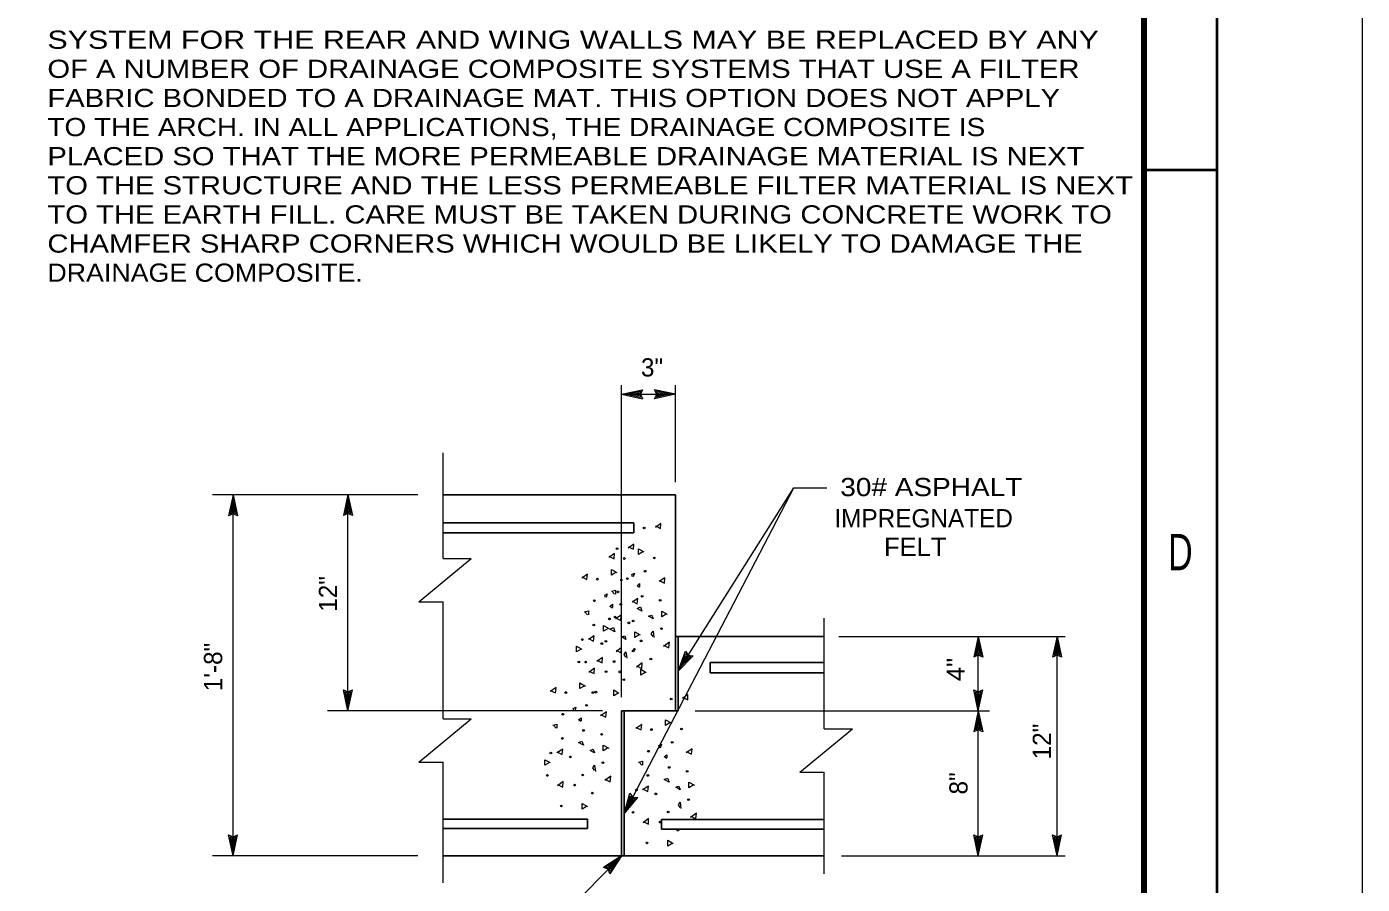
# Model space of a CAD drawing. Extents: x -22.3 to 19.7, y -11.8 to 18.2.
# Drawn here: x 10.52 to 19.69, y 6.25 to 12.14 of the extents above; entities that cross this region are included whole.
import ezdxf
from ezdxf.enums import TextEntityAlignment as Align

# ---------------------------------------------------------------- set-up
doc = ezdxf.new("R2010")
doc.units = 0
doc.header["$LTSCALE"] = 0.05
doc.layers.add('1', color=7, linetype='Continuous', lineweight=13)
doc.layers.add('2', color=7, linetype='Continuous', lineweight=13)

msp = doc.modelspace()

# ---------------------------------------------------------------- linework, layer by layer
at = {"layer": '1', "lineweight": 40}
msp.add_line((18.19058, 11.16031), (18.69058, 11.16031), dxfattribs=at)
at = {"layer": '1'}
for p, q in [((14.60258, 7.53931), (14.60258, 9.68231)), ((14.60358, 9.61931), (14.74758, 9.65031)), ((14.64058, 9.61931), (14.73458, 9.63931)), ((14.73458, 9.63931), (14.72558, 9.61931)), ((14.97458, 9.61931), (14.83058, 9.65031)), ((14.93758, 9.61931), (14.84358, 9.63931)), ((14.85258, 9.61931), (14.84358, 9.63931)), ((14.97458, 9.01431), (14.97458, 9.68231)), ((14.60358, 9.61931), (14.97458, 9.61931)), ((14.60358, 9.61931), (14.74758, 9.58831)), ((14.64058, 9.61931), (14.73458, 9.59931)), ((14.67658, 9.61931), (14.72158, 9.62931)), ((14.67658, 9.61931), (14.72158, 9.61031)), ((14.72158, 9.62931), (14.71758, 9.61931)), ((14.71758, 9.61931), (14.72158, 9.61031)), ((14.72558, 9.61931), (14.73458, 9.59931)), ((14.97458, 9.61931), (14.83058, 9.58831)), ((14.93758, 9.61931), (14.84358, 9.59931)), ((14.84358, 9.59931), (14.85258, 9.61931)), ((14.90158, 9.61931), (14.85658, 9.62831)), ((14.86058, 9.61931), (14.85658, 9.62831)), ((14.90158, 9.61931), (14.85658, 9.60931)), ((14.85658, 9.60931), (14.86058, 9.61931)), ((13.37858, 8.49131), (13.37858, 9.21731)), ((13.20358, 8.92831), (11.79458, 8.92831)), ((11.93558, 8.92831), (11.90458, 8.78431)), ((11.93558, 6.44931), (11.93558, 8.92831)), ((11.93558, 8.92831), (11.96658, 8.78431)), ((12.72458, 8.93031), (12.69358, 8.78631)), ((12.72458, 7.44431), (12.72458, 8.93031)), ((12.72458, 8.93031), (12.75558, 8.78631)), ((14.99158, 7.71731), (15.78558, 8.97631)), ((11.93558, 8.89131), (11.91558, 8.79731)), ((11.93558, 8.80631), (11.91558, 8.79731)), ((11.93558, 8.85531), (11.92658, 8.81031)), ((11.93558, 8.81431), (11.92658, 8.81031)), ((11.93558, 8.89131), (11.95558, 8.79731)), ((11.93558, 8.85531), (11.94558, 8.81031)), ((11.94558, 8.81031), (11.93558, 8.81431)), ((11.95558, 8.79731), (11.93558, 8.80631)), ((12.72458, 8.89331), (12.70458, 8.79931)), ((12.72458, 8.80831), (12.70458, 8.79931)), ((12.72458, 8.85731), (12.71558, 8.81231)), ((12.72458, 8.81631), (12.71558, 8.81231)), ((12.72458, 8.89331), (12.74458, 8.79931)), ((12.72458, 8.85731), (12.73458, 8.81231)), ((12.73458, 8.81231), (12.72458, 8.81631)), ((12.74458, 8.79931), (12.72458, 8.80831)), ((13.21058, 8.19431), (13.57158, 8.49131)), ((13.37858, 8.49131), (13.57158, 8.49131)), ((13.21058, 8.19431), (13.37858, 8.19431)), ((13.37858, 7.38931), (13.37858, 8.19431)), ((15.99558, 7.32131), (15.99558, 8.08231)), ((16.09558, 7.95631), (17.65058, 7.95631)), ((17.05358, 7.95631), (17.02258, 7.81231)), ((17.05358, 7.91931), (17.03358, 7.82531)), ((17.05358, 7.95631), (17.08458, 7.81231)), ((17.05358, 7.91931), (17.07358, 7.82531)), ((17.59458, 7.95731), (17.56358, 7.81331)), ((17.59458, 7.92031), (17.57458, 7.82631)), ((17.59458, 6.44931), (17.59458, 7.95731)), ((17.59458, 7.95731), (17.62558, 7.81331)), ((17.59458, 7.92031), (17.61458, 7.82631)), ((14.99158, 7.71731), (15.04258, 7.85531)), ((14.99158, 7.71731), (15.09458, 7.82231)), ((15.01158, 7.74831), (15.04458, 7.83831)), ((15.01158, 7.74831), (15.07858, 7.81731)), ((15.03058, 7.77931), (15.04558, 7.82231)), ((15.03058, 7.77931), (15.06258, 7.81231)), ((15.04458, 7.83831), (15.05658, 7.82031)), ((15.04558, 7.82231), (15.05258, 7.81331)), ((15.05258, 7.81331), (15.06258, 7.81231)), ((15.05658, 7.82031), (15.07858, 7.81731)), ((17.05358, 7.83431), (17.03358, 7.82531)), ((17.05358, 7.88331), (17.04458, 7.83831)), ((17.05358, 7.84231), (17.04458, 7.83831)), ((17.05358, 7.88331), (17.06358, 7.83831)), ((17.06358, 7.83831), (17.05358, 7.84231)), ((17.07358, 7.82531), (17.05358, 7.83431)), ((17.59458, 7.83531), (17.57458, 7.82631)), ((17.59458, 7.88431), (17.58558, 7.83931)), ((17.59458, 7.84331), (17.58558, 7.83931)), ((17.59458, 7.88431), (17.60458, 7.83931)), ((17.60458, 7.83931), (17.59458, 7.84331)), ((17.61458, 7.82631), (17.59458, 7.83531)), ((12.72458, 7.44431), (12.69358, 7.58831)), ((12.72458, 7.48131), (12.70458, 7.57531)), ((12.70458, 7.57531), (12.72458, 7.56631)), ((12.72458, 7.51731), (12.71458, 7.56231)), ((12.71458, 7.56231), (12.72458, 7.55831)), ((12.72458, 7.44431), (12.75558, 7.58831)), ((12.72458, 7.48131), (12.74458, 7.57531)), ((12.72458, 7.56631), (12.74458, 7.57531)), ((12.72458, 7.51731), (12.73358, 7.56231)), ((12.72458, 7.55831), (12.73358, 7.56231)), ((17.05358, 7.44431), (17.02258, 7.58831)), ((17.05358, 7.48131), (17.03358, 7.57531)), ((17.03358, 7.57531), (17.05358, 7.56631)), ((17.05358, 7.51731), (17.04358, 7.56231)), ((17.04358, 7.56231), (17.05358, 7.55831)), ((17.05358, 7.44431), (17.08458, 7.58831)), ((17.05358, 7.48131), (17.07358, 7.57531)), ((17.05358, 7.56631), (17.07358, 7.57531)), ((17.05358, 7.51731), (17.06258, 7.56231)), ((17.05358, 7.55831), (17.06258, 7.56231)), ((14.47158, 7.44431), (12.58358, 7.44431)), ((15.10958, 7.44431), (17.12958, 7.44431)), ((17.05358, 7.44431), (17.02258, 7.30031)), ((17.05358, 7.44431), (17.08458, 7.30031)), ((13.21058, 7.09231), (13.57158, 7.38931)), ((13.37858, 7.38931), (13.57158, 7.38931)), ((17.05358, 7.40731), (17.03358, 7.31331)), ((17.05358, 7.37131), (17.04458, 7.32631)), ((17.05358, 7.40731), (17.07358, 7.31331)), ((17.05358, 7.37131), (17.06358, 7.32631)), ((15.82758, 7.02431), (16.18858, 7.32131)), ((15.99558, 7.32131), (16.18858, 7.32131)), ((17.05358, 7.32231), (17.03358, 7.31331)), ((17.05358, 7.33031), (17.04458, 7.32631)), ((17.06358, 7.32631), (17.05358, 7.33031)), ((17.07358, 7.31331), (17.05358, 7.32231)), ((13.21058, 7.09231), (13.37858, 7.09231)), ((13.37858, 6.26331), (13.37858, 7.09231)), ((15.82758, 7.02431), (15.99558, 7.02431)), ((15.99558, 6.32531), (15.99558, 7.02431)), ((14.62158, 6.73631), (14.66058, 6.87831)), ((14.62158, 6.73631), (14.71558, 6.84931)), ((14.63858, 6.76931), (14.66458, 6.86131)), ((14.63858, 6.76931), (14.69958, 6.84331)), ((14.65558, 6.80131), (14.66758, 6.84531)), ((14.65558, 6.80131), (14.68358, 6.83731)), ((14.66458, 6.86131), (14.67758, 6.84431)), ((14.66758, 6.84531), (14.67458, 6.83731)), ((14.67458, 6.83731), (14.68358, 6.83731)), ((14.67758, 6.84431), (14.69958, 6.84331)), ((11.93558, 6.44931), (11.90458, 6.59331)), ((11.93558, 6.48631), (11.91558, 6.58031)), ((11.91558, 6.58031), (11.93558, 6.57131)), ((11.93558, 6.52231), (11.92558, 6.56731)), ((11.92558, 6.56731), (11.93558, 6.56331)), ((11.93558, 6.44931), (11.96658, 6.59331)), ((11.93558, 6.48631), (11.95558, 6.58031)), ((11.93558, 6.57131), (11.95558, 6.58031)), ((11.93558, 6.52231), (11.94458, 6.56731)), ((11.93558, 6.56331), (11.94458, 6.56731)), ((17.05358, 6.44931), (17.02258, 6.59331)), ((17.05358, 6.48631), (17.03358, 6.58031)), ((17.03358, 6.58031), (17.05358, 6.57131)), ((17.05358, 6.52231), (17.04358, 6.56731)), ((17.04358, 6.56731), (17.05358, 6.56331)), ((17.05358, 6.44931), (17.08458, 6.59331)), ((17.05358, 6.48631), (17.07358, 6.58031)), ((17.05358, 6.57131), (17.07358, 6.58031)), ((17.05358, 6.52231), (17.06258, 6.56731)), ((17.05358, 6.56331), (17.06258, 6.56731)), ((17.59458, 6.44931), (17.56358, 6.59331)), ((17.59458, 6.48631), (17.57458, 6.58031)), ((17.57458, 6.58031), (17.59458, 6.57131)), ((17.59458, 6.52231), (17.58458, 6.56731)), ((17.58458, 6.56731), (17.59458, 6.56331)), ((17.59458, 6.44931), (17.62558, 6.59331)), ((17.59458, 6.48631), (17.61458, 6.58031)), ((17.59458, 6.57131), (17.61458, 6.58031)), ((17.59458, 6.52231), (17.60358, 6.56731)), ((17.59458, 6.56331), (17.60358, 6.56731)), ((13.20358, 6.44931), (11.79458, 6.44931)), ((14.60258, 6.44931), (14.47958, 6.36831)), ((14.57658, 6.42331), (14.49658, 6.37031)), ((14.60258, 6.44931), (14.52358, 6.32531)), ((14.57658, 6.42331), (14.52558, 6.34231)), ((16.11458, 6.44931), (17.65058, 6.44931)), ((14.51758, 6.36231), (14.49658, 6.37031)), ((14.55158, 6.39731), (14.51358, 6.37131)), ((14.52258, 6.36831), (14.51358, 6.37131)), ((14.52558, 6.34231), (14.51758, 6.36231)), ((14.52658, 6.35831), (14.52258, 6.36831)), ((14.55158, 6.39731), (14.52658, 6.35831))]:
    msp.add_line(p, q, dxfattribs=at)
at = {"layer": '1', "lineweight": 25}
for p, q in [((13.37858, 8.92831), (14.97458, 8.92831)), ((14.97458, 7.44431), (14.97458, 8.92831)), ((13.37858, 8.73631), (14.68858, 8.73631)), ((14.68858, 8.66831), (14.68858, 8.73631)), ((13.37858, 8.66831), (14.68858, 8.66831)), ((14.97458, 7.95631), (15.99558, 7.95631)), ((14.99158, 7.44431), (14.99158, 7.95631)), ((15.21258, 7.77631), (15.99358, 7.77631)), ((15.21258, 7.70531), (15.21258, 7.77631)), ((15.21258, 7.70531), (15.99358, 7.70531)), ((14.60258, 6.44931), (14.60258, 7.44431)), ((14.60258, 7.44431), (14.99158, 7.44431)), ((14.62158, 6.44931), (14.62158, 7.44431)), ((13.37858, 6.70131), (14.37058, 6.70131)), ((14.37058, 6.63631), (14.37058, 6.70131)), ((14.87858, 6.69731), (15.99558, 6.69731)), ((14.87858, 6.63131), (14.87858, 6.69731)), ((13.37858, 6.63631), (14.37058, 6.63631)), ((14.87858, 6.63131), (15.99558, 6.63131)), ((13.37858, 6.44931), (15.99558, 6.44931))]:
    msp.add_line(p, q, dxfattribs=at)
at = {"layer": '1'}
for points in [[(-22.30942, 18.16031), (19.69058, 18.16031), (19.69058, -11.83969)], [(14.74758, 9.65031), (14.73358, 9.61931), (14.74758, 9.58831)], [(14.83058, 9.58831), (14.84458, 9.61931), (14.83058, 9.65031)], [(14.62158, 6.73631), (15.78558, 8.97631), (16.01258, 8.97631)], [(11.96658, 8.78431), (11.93558, 8.79831), (11.90458, 8.78431)], [(12.75558, 8.78631), (12.72458, 8.80031), (12.69358, 8.78631)], [(17.05358, 6.44931), (17.05358, 7.44431), (17.05358, 7.95631)], [(15.04258, 7.85531), (15.06058, 7.82731), (15.09458, 7.82231)], [(17.08458, 7.81231), (17.05358, 7.82631), (17.02258, 7.81231)], [(17.62558, 7.81331), (17.59458, 7.82731), (17.56358, 7.81331)], [(12.69358, 7.58831), (12.72458, 7.57431), (12.75558, 7.58831)], [(17.02258, 7.58831), (17.05358, 7.57431), (17.08458, 7.58831)], [(17.08458, 7.30031), (17.05358, 7.31431), (17.02258, 7.30031)], [(14.66058, 6.87831), (14.68158, 6.85131), (14.71558, 6.84931)], [(11.90458, 6.59331), (11.93558, 6.57931), (11.96658, 6.59331)], [(17.02258, 6.59331), (17.05358, 6.57931), (17.08458, 6.59331)], [(17.56358, 6.59331), (17.59458, 6.57931), (17.62558, 6.59331)], [(14.60258, 6.44931), (13.31658, 5.13931), (12.74958, 5.13931)], [(14.52358, 6.32531), (14.51158, 6.35631), (14.47958, 6.36831)]]:
    msp.add_lwpolyline(points, dxfattribs=at)
at = {"layer": '1', "lineweight": 40}
msp.add_lwpolyline([(-21.30942, -10.83969), (-21.30942, 17.16031), (18.69058, 17.16031), (18.69058, -10.83969)], close=True, dxfattribs=at)
at = {"layer": '1', "lineweight": 90}
msp.add_lwpolyline([(-19.80942, 16.66031), (18.19058, 16.66031), (18.19058, -10.33969), (-19.80942, -10.33969)], close=True, dxfattribs=at)
at = {"layer": '2'}
for p, q in [((14.55558, 8.24631), (14.53758, 8.26631)), ((14.36958, 8.10431), (14.35158, 8.12431)), ((14.15358, 7.32531), (14.13558, 7.34531)), ((14.74158, 7.07131), (14.72358, 7.09131))]:
    msp.add_line(p, q, dxfattribs=at)
for points in [[(14.83558, 8.71431), (14.87158, 8.69631), (14.87358, 8.73231), (14.83558, 8.70431)], [(14.64958, 8.57231), (14.68558, 8.55431), (14.68758, 8.59031), (14.64958, 8.56231)], [(14.74958, 8.53631), (14.71958, 8.51831), (14.71958, 8.55831), (14.75758, 8.53631)], [(14.51558, 8.50631), (14.55158, 8.48831), (14.55558, 8.52631), (14.51558, 8.49831)], [(14.32958, 8.36431), (14.36558, 8.34631), (14.36958, 8.38431), (14.32958, 8.35631)], [(14.56358, 8.39431), (14.53358, 8.37631), (14.53358, 8.41631), (14.57158, 8.39431)], [(14.67958, 8.36431), (14.67358, 8.38231), (14.69158, 8.39031), (14.68358, 8.36431)], [(14.86158, 8.34031), (14.89758, 8.32231), (14.90158, 8.35831), (14.86158, 8.33231)], [(14.53358, 8.26631), (14.56158, 8.27431), (14.56158, 8.24631)], [(14.72758, 8.29231), (14.70958, 8.30431), (14.72758, 8.31831), (14.72758, 8.29631)], [(14.49358, 8.22231), (14.48758, 8.24031), (14.50558, 8.24831), (14.49758, 8.22231)], [(14.54158, 8.15031), (14.52358, 8.16231), (14.54158, 8.17631), (14.54158, 8.15431)], [(14.67558, 8.19831), (14.71158, 8.18031), (14.71558, 8.21631), (14.67558, 8.19031)], [(14.34758, 8.12431), (14.37558, 8.13231), (14.37558, 8.10431)], [(14.56158, 8.08431), (14.59758, 8.06631), (14.60158, 8.10231), (14.56158, 8.07631)], [(14.90958, 8.10831), (14.87958, 8.09031), (14.87958, 8.13031), (14.91758, 8.10831)], [(14.51158, 8.01031), (14.47958, 7.99231), (14.47958, 8.03031), (14.51558, 8.01031)], [(14.72358, 7.96631), (14.69358, 7.94831), (14.69358, 7.98831), (14.73158, 7.96631)], [(14.81958, 7.95631), (14.80758, 7.97431), (14.81958, 7.99231), (14.82558, 7.94831)], [(14.32558, 7.86831), (14.29358, 7.85031), (14.29358, 7.88831), (14.32958, 7.86831)], [(14.37558, 7.94231), (14.41158, 7.92431), (14.41558, 7.96031), (14.37558, 7.93431)], [(14.89158, 7.89631), (14.92758, 7.87831), (14.93158, 7.91631), (14.89158, 7.88631)], [(14.43358, 7.79331), (14.46958, 7.77531), (14.47158, 7.81131), (14.43358, 7.78331)], [(14.56558, 7.86031), (14.60158, 7.84231), (14.60358, 7.88031), (14.56558, 7.85031)], [(14.63358, 7.81431), (14.62158, 7.83231), (14.63358, 7.85031), (14.63958, 7.80631)], [(14.37958, 7.71831), (14.41558, 7.70031), (14.41758, 7.73831), (14.37958, 7.70831)], [(14.70558, 7.75431), (14.74158, 7.73631), (14.74558, 7.77431), (14.70558, 7.74431)], [(14.76558, 7.70831), (14.73558, 7.69031), (14.73558, 7.73031), (14.77158, 7.70831)], [(14.34758, 7.61531), (14.31758, 7.59731), (14.31758, 7.63731), (14.35558, 7.61531)], [(14.11358, 7.58531), (14.14958, 7.56731), (14.15358, 7.60531), (14.11358, 7.57731)], [(14.57958, 7.56631), (14.54958, 7.54831), (14.54958, 7.58831), (14.58558, 7.56631)], [(15.02158, 7.53931), (15.05758, 7.52131), (15.05958, 7.55731), (15.02158, 7.52931)], [(14.27758, 7.44331), (14.27158, 7.46131), (14.28958, 7.46931), (14.28158, 7.44331)], [(14.45958, 7.41931), (14.49558, 7.40131), (14.49958, 7.43731), (14.45958, 7.41131)], [(14.13158, 7.34531), (14.15958, 7.35331), (14.15958, 7.32531)], [(14.32558, 7.37131), (14.30758, 7.38331), (14.32558, 7.39731), (14.32558, 7.37531)], [(14.70158, 7.33131), (14.73758, 7.31331), (14.74158, 7.35131), (14.70158, 7.32331)], [(14.93558, 7.36131), (14.90558, 7.34331), (14.90558, 7.38331), (14.94358, 7.36131)], [(14.15958, 7.16331), (14.19558, 7.14531), (14.19958, 7.18131), (14.15958, 7.15531)], [(14.50758, 7.18731), (14.47758, 7.16931), (14.47758, 7.20931), (14.51558, 7.18731)], [(14.86558, 7.18931), (14.85958, 7.20731), (14.87758, 7.21531), (14.86958, 7.18931)], [(15.04758, 7.16531), (15.08358, 7.14731), (15.08758, 7.18331), (15.04758, 7.15731)], [(14.10958, 7.08931), (14.07758, 7.07131), (14.07758, 7.10931), (14.11358, 7.08931)], [(14.41758, 7.03531), (14.40558, 7.05331), (14.41758, 7.07131), (14.42358, 7.02731)], [(14.71958, 7.09131), (14.74758, 7.09931), (14.74758, 7.07131)], [(14.91358, 7.11731), (14.89558, 7.12931), (14.91358, 7.14331), (14.91358, 7.12131)], [(14.48958, 6.97531), (14.52558, 6.95731), (14.52958, 6.99531), (14.48958, 6.96531)], [(14.16358, 6.93931), (14.19958, 6.92131), (14.20158, 6.95931), (14.16358, 6.92931)], [(14.74758, 6.90931), (14.78358, 6.89131), (14.78758, 6.92731), (14.74758, 6.90131)], [(15.09558, 6.93331), (15.06558, 6.91531), (15.06558, 6.95531), (15.10358, 6.93331)], [(14.36358, 6.78731), (14.33358, 6.76931), (14.33358, 6.80931), (14.36958, 6.78731)], [(14.69758, 6.83531), (14.66558, 6.81731), (14.66558, 6.85531), (14.70158, 6.83531)], [(15.00558, 6.78131), (14.99358, 6.79931), (15.00558, 6.81731), (15.01158, 6.77331)], [(14.75158, 6.68531), (14.78758, 6.66731), (14.78958, 6.70531), (14.75158, 6.67531)], [(15.07758, 6.72131), (15.11358, 6.70331), (15.11758, 6.74131), (15.07758, 6.71131)], [(14.95158, 6.53331), (14.92158, 6.51531), (14.92158, 6.55531), (14.95758, 6.53331)]]:
    msp.add_lwpolyline(points, dxfattribs=at)
for points in [[(14.74358, 8.13031), (14.70958, 8.14831), (14.73358, 8.15831)], [(14.81958, 8.07631), (14.78958, 8.09431), (14.81158, 8.10231)], [(14.55758, 7.98831), (14.52358, 8.00631), (14.54758, 8.01631)], [(14.63358, 7.93431), (14.60358, 7.95231), (14.62558, 7.96031)], [(14.34158, 7.20931), (14.30758, 7.22731), (14.33158, 7.23731)], [(14.41758, 7.15531), (14.38758, 7.17331), (14.40958, 7.18131)], [(14.92958, 6.95531), (14.89558, 6.97331), (14.91958, 6.98331)], [(15.00558, 6.90131), (14.97558, 6.91931), (14.99758, 6.92731)]]:
    msp.add_lwpolyline(points, close=True, dxfattribs=at)
for centre in [(14.75873, 8.70071), (14.57273, 8.55871), (14.62283, 8.49101), (14.82893, 8.49461), (14.43683, 8.34901), (14.60213, 8.34251), (14.64293, 8.35261), (14.76503, 8.40371), (14.57903, 8.26171), (14.41613, 8.20051), (14.59853, 8.17601), (14.74433, 8.23091), (14.86853, 8.20391), (14.52023, 8.07611), (14.55833, 8.08891), (14.41253, 8.03401), (14.65343, 8.04911), (14.68253, 8.06191), (14.87753, 8.00951), (14.33423, 7.93411), (14.46743, 7.90711), (14.49593, 7.92221), (14.73803, 7.92491), (14.68313, 7.85561), (14.69153, 7.86751), (14.80463, 7.80071), (14.30993, 7.78021), (14.35673, 7.77971), (14.49713, 7.71361), (14.55203, 7.78291), (14.59223, 7.71251), (14.61863, 7.65871), (14.22083, 7.57001), (14.40623, 7.57051), (14.42693, 7.57361), (14.94473, 7.52571), (14.36303, 7.48271), (14.20013, 7.42151), (14.19653, 7.25501), (14.34233, 7.30991), (14.46653, 7.28291), (14.80883, 7.31601), (15.01493, 7.31961), (14.11823, 7.15511), (14.78813, 7.16751), (14.95103, 7.22871), (14.25143, 7.12811), (14.47553, 7.08851), (14.09393, 7.00121), (14.33603, 7.00391), (14.78453, 7.00101), (14.93033, 7.05591), (15.05453, 7.02891), (14.28113, 6.93461), (14.40263, 6.87971), (14.70623, 6.90111), (14.83943, 6.87411), (14.19023, 6.79151), (15.06353, 6.83451), (14.68193, 6.74721), (14.92403, 6.74991), (14.86913, 6.68061), (14.99063, 6.62571), (14.77823, 6.53751)]:
    msp.add_circle(centre, 0.00585, dxfattribs=at)

# ---------------------------------------------------------------- texts
at = {"layer": '1'}
for s, width, p in [('SYSTEM FOR THE REAR AND WING WALLS MAY BE REPLACED BY ANY', 1.25, (10.66025, 11.99198)), ('OF A NUMBER OF DRAINAGE COMPOSITE SYSTEMS THAT USE A FILTER', 1.2, (10.66025, 11.79198)), ('FABRIC BONDED TO A DRAINAGE MAT. THIS OPTION DOES NOT APPLY', 1.2, (10.66025, 11.59198)), ('TO THE ARCH. IN ALL APPLICATIONS, THE DRAINAGE COMPOSITE IS', 1.15, (10.66025, 11.39198)), ('PLACED SO THAT THE MORE PERMEABLE DRAINAGE MATERIAL IS NEXT', 1.2, (10.66025, 11.19198)), ('TO THE STRUCTURE AND THE LESS PERMEABLE FILTER MATERIAL IS NEXT', 1.2, (10.66025, 10.99198)), ('TO THE EARTH FILL. CARE MUST BE TAKEN DURING CONCRETE WORK TO', 1.2, (10.66025, 10.79198)), ('CHAMFER SHARP CORNERS WHICH WOULD BE LIKELY TO DAMAGE THE', 1.2, (10.66025, 10.59198)), ('DRAINAGE COMPOSITE.', 1.1, (10.66025, 10.39198)), ('30# ASPHALT', 1.15, (16.10558, 8.91931))]:
    msp.add_text(s, height=0.125, dxfattribs=dict(at, width=width)).set_placement(p)
for s, p in [('3"', (14.81258, 9.74131)), ('IMPREGNATED', (16.67808, 8.70531))]:
    msp.add_text(s, height=0.125, dxfattribs=at).set_placement(p, align=Align.CENTER)
for s, height, width, p in [('FELT', 0.125, 1.05, (16.62058, 8.50831)), ('D', 0.25, 0.7, (18.44108, 8.41031))]:
    msp.add_text(s, height=height, dxfattribs=dict(at, width=width)).set_placement(p, align=Align.CENTER)
for s, p in [('12"', (12.64958, 8.24781)), ('1\'-8"', (11.86058, 7.74581)), ('12"', (17.55258, 7.23381)), ('8"', (16.97958, 6.94631))]:
    msp.add_text(s, height=0.125, rotation=90, dxfattribs=at).set_placement(p, align=Align.CENTER)
at = {"layer": '1', "width": 1.05}
msp.add_text('4"', height=0.125, rotation=90, dxfattribs=at).set_placement((16.96058, 7.72831), align=Align.CENTER)

doc.saveas('drawing.dxf')
